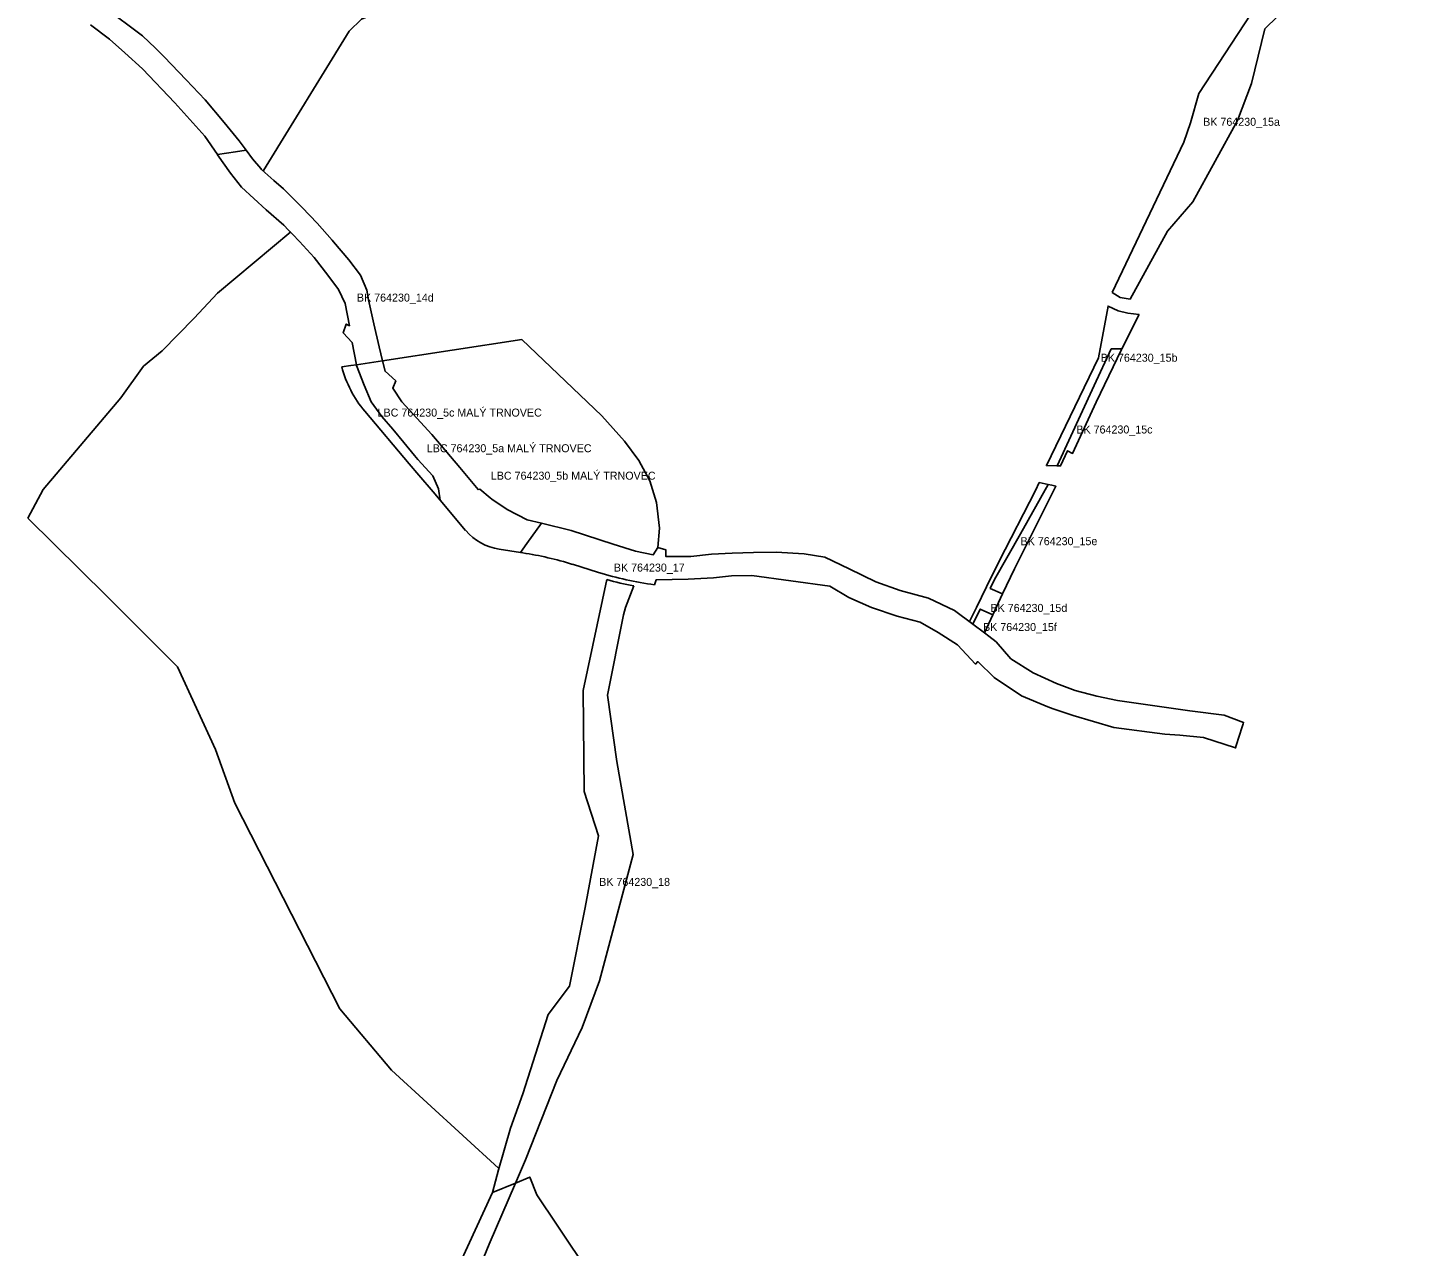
# Model space of a CAD drawing. Extents: x -521616 to -516782, y -1190061 to -1184927.
# Drawn here: x -518534 to -517316, y -1188489 to -1187423 of the extents above; entities that cross this region are included whole.
import ezdxf

# ---------------------------------------------------------------- set-up
doc = ezdxf.new("R2010")
doc.units = 0
for name, color, linetype in [('i_prvek_l_n', 7, 'Continuous'), ('i_prvek_l_s', 7, 'Continuous'), ('LBC_n', 7, 'Continuous'), ('LBC_s', 7, 'Continuous'), ('LBK_n', 7, 'Continuous'), ('LBK_s', 7, 'Continuous')]:
    doc.layers.add(name, color=color, linetype=linetype)

msp = doc.modelspace()

# ---------------------------------------------------------------- linework, layer by layer
at = {"layer": 'i_prvek_l_n'}
for points in [[(-518327.8, -1187548.3), (-518252.9, -1187426.5), (-518242, -1187415.8), (-518235, -1187412.9), (-518191.3, -1187412)], [(-518533.9, -1187852.4), (-518520.4, -1187827.3), (-518452.6, -1187747.2), (-518432.7, -1187719.6), (-518416.4, -1187706.2), (-518388.3, -1187677.4), (-518367.9, -1187655.6), (-518304, -1187602)]]:
    msp.add_lwpolyline(points, dxfattribs=at)
at = {"layer": 'i_prvek_l_s'}
msp.add_lwpolyline([(-518122.2, -1188421.1), (-518215.8, -1188335.4), (-518261.1, -1188281.7), (-518352.9, -1188101.7), (-518369.9, -1188054.9), (-518403.1, -1187982.6), (-518465.1, -1187920.5), (-518533.9, -1187852.4)], dxfattribs=at)
at = {"layer": 'LBC_n'}
for points in [[(-518223.7, -1187714.7), (-518102, -1187696.1), (-518031.8, -1187762.8), (-518012.2, -1187785.1), (-517999.6, -1187802), (-517989.8, -1187819.8), (-517984, -1187838.7), (-517981.5, -1187861.2), (-517982.9, -1187878.1), (-517987, -1187884.5), (-518002.4, -1187881.3), (-518021.9, -1187875.1), (-518058.6, -1187863.4), (-518084.7, -1187856.9), (-518097.1, -1187853.8), (-518114.6, -1187845), (-518128.2, -1187835.9), (-518129.6, -1187834.7), (-518138.5, -1187827.1), (-518140.1, -1187827.4), (-518156.2, -1187808.2), (-518180.6, -1187779.3), (-518206.7, -1187750.6), (-518214.8, -1187738.7), (-518212.1, -1187732.3), (-518221.4, -1187724)], [(-518107.5, -1188434.2), (-518094.9, -1188429), (-518088.8, -1188444.4), (-518071, -1188471), (-517982, -1188604), (-517899.2, -1188742.7), (-518042.7, -1188683.1), (-518186.2, -1188623.6), (-518130.3, -1188487.5)]]:
    msp.add_lwpolyline(points, close=True, dxfattribs=at)
msp.add_lwpolyline([(-518259.3, -1187720.1), (-518251.5, -1187718.9), (-518246.6, -1187718.2), (-518246.4, -1187718.8), (-518239.9, -1187736), (-518233.5, -1187750.6), (-518224.4, -1187763.4), (-518214.8, -1187774.7), (-518205.2, -1187786.3), (-518195.8, -1187797.6), (-518192.9, -1187801.1), (-518179.6, -1187815.4), (-518174.7, -1187826.8), (-518173.4, -1187836.7), (-518179.5, -1187829.5), (-518191.9, -1187814.8), (-518200.3, -1187804.9), (-518239.2, -1187758.9)], dxfattribs=at)
msp.add_arc((-518164.4, -1187695.6), 98, 194.4563, 220.234, dxfattribs=at)
at = {"layer": 'LBC_s'}
for points in [[(-518179.6, -1187815.4), (-518192.9, -1187801.1), (-518195.8, -1187797.6), (-518205.2, -1187786.3), (-518214.8, -1187774.7), (-518224.4, -1187763.4), (-518233.5, -1187750.6), (-518239.9, -1187736), (-518246.4, -1187718.8), (-518246.6, -1187718.2), (-518223.7, -1187714.7), (-518221.4, -1187724), (-518212.1, -1187732.3), (-518214.8, -1187738.7), (-518206.7, -1187750.6), (-518180.6, -1187779.3), (-518156.2, -1187808.2), (-518140.1, -1187827.4), (-518138.5, -1187827.1), (-518129.6, -1187834.7), (-518128.2, -1187835.9), (-518114.6, -1187845), (-518097.1, -1187853.8), (-518084.7, -1187856.9), (-518097.4, -1187874.7)], [(-518151, -1187863.2), (-518173.4, -1187836.7), (-518174.7, -1187826.8), (-518179.6, -1187815.4)], [(-518097.4, -1187874.7), (-518102.9, -1187882.5), (-518121.6, -1187879.6)], [(-518178.1, -1188552.2), (-518127.5, -1188442.4), (-518107.5, -1188434.2), (-518130.3, -1188487.5), (-518186.2, -1188623.6)]]:
    msp.add_lwpolyline(points, dxfattribs=at)
msp.add_arc((-518114.3, -1187832.2), 48, 220.2323, 261.2546, dxfattribs=at)
at = {"layer": 'LBK_n'}
for points in [[(-518352.3, -1187532), (-518343, -1187530.5), (-518337.4, -1187538), (-518330.2, -1187546.5), (-518329.5, -1187547.4), (-518326.5, -1187550.1), (-518318.7, -1187557.1), (-518310.4, -1187564.3), (-518294.1, -1187580.8), (-518281, -1187594.4), (-518267.8, -1187609.4), (-518266.5, -1187610.8), (-518253.1, -1187626.6), (-518243.1, -1187639.9), (-518237.5, -1187652.9), (-518235.9, -1187661.6), (-518231.2, -1187682.4), (-518226.7, -1187702.5), (-518223.7, -1187714.7), (-518246.6, -1187718.2), (-518250.4, -1187698.8), (-518258, -1187690.3), (-518255.4, -1187682.6), (-518252.6, -1187684.1), (-518256.3, -1187664.8), (-518262.3, -1187652.3), (-518271.6, -1187639.8), (-518283.6, -1187624.5), (-518296.4, -1187610.4), (-518302.4, -1187604), (-518304.1, -1187602.2), (-518305.9, -1187600.4), (-518310, -1187596), (-518325.6, -1187582.7), (-518336.4, -1187572.9), (-518347, -1187562.8), (-518356.8, -1187550.6), (-518367.9, -1187534.7), (-518368.1, -1187534.4)], [(-517684.5, -1187890.1), (-517652.7, -1187828.4), (-517649.4, -1187821.4), (-517641.6, -1187823), (-517665.7, -1187866.1), (-517688.4, -1187906.2), (-517692.2, -1187914), (-517681.4, -1187918.8), (-517689.8, -1187936.9), (-517701, -1187932), (-517707.4, -1187945.2), (-517710.4, -1187943), (-517704.3, -1187930.6), (-517695.5, -1187912.6)]]:
    msp.add_lwpolyline(points, close=True, dxfattribs=at)
for points in [[(-517586.4, -1187704.3), (-517601.2, -1187736.4), (-517633.7, -1187806.7), (-517643.1, -1187806.5), (-517597.6, -1187712.2), (-517589.2, -1187666.9), (-517580.3, -1187671.2), (-517572, -1187673.1)], [(-517562, -1187674.2), (-517577.2, -1187704.4), (-517586.4, -1187704.3)], [(-517572, -1187673.1), (-517562, -1187674.2)]]:
    msp.add_lwpolyline(points, dxfattribs=at)
at = {"layer": 'LBK_s'}
for points in [[(-517585.7, -1187655.1), (-517522.9, -1187523.6), (-517517, -1187506.5), (-517509.9, -1187480.8), (-517441.7, -1187376.6), (-517361.8, -1187252.7), (-517351.7, -1187237.2), (-517316.2, -1187258.5), (-517347.4, -1187309.2), (-517384.1, -1187358), (-517452.1, -1187424.5), (-517463.8, -1187472.2), (-517476, -1187504.6), (-517514.9, -1187575.8), (-517537.2, -1187601.4), (-517569.9, -1187660.8), (-517578.6, -1187659.3), (-517585.7, -1187655.1)], [(-517681.4, -1187918.8), (-517692.2, -1187914), (-517688.4, -1187906.2), (-517665.7, -1187866.1), (-517641.6, -1187823), (-517638.3, -1187823.7), (-517634.7, -1187824.6), (-517671.1, -1187896.8)], [(-517701, -1187932), (-517689.8, -1187936.9), (-517697.3, -1187952.8), (-517707.4, -1187945.2)]]:
    msp.add_lwpolyline(points, close=True, dxfattribs=at)
for points in [[(-518467.3, -1187405.3), (-518433.5, -1187430.6), (-518422.4, -1187441.4), (-518414.7, -1187448.9), (-518395.5, -1187469), (-518378.8, -1187486.6), (-518362.1, -1187506.3), (-518349.2, -1187522.3), (-518343, -1187530.5)], [(-518368.1, -1187534.4), (-518379.1, -1187518.4), (-518405.4, -1187489.2), (-518433.6, -1187459.4), (-518449.2, -1187445.4), (-518462.6, -1187433.3), (-518479, -1187420.8)], [(-518343, -1187530.5), (-518352.3, -1187532), (-518368.1, -1187534.4)], [(-517577.2, -1187704.4), (-517577.5, -1187704.9), (-517599.5, -1187750.9), (-517620.2, -1187795.8), (-517624.5, -1187793.5), (-517630.7, -1187806.8), (-517633.7, -1187806.7), (-517601.2, -1187736.4), (-517586.4, -1187704.3)], [(-517586.4, -1187704.3), (-517577.2, -1187704.4)], [(-518102.9, -1187882.5), (-518097.4, -1187874.7), (-518084.7, -1187856.9), (-518058.6, -1187863.4), (-518021.9, -1187875.1), (-518002.4, -1187881.3), (-517987, -1187884.5), (-517982.9, -1187878.1), (-517976, -1187880.1), (-517976, -1187885.9), (-517954.2, -1187886.1), (-517936, -1187884), (-517917.8, -1187883), (-517899.4, -1187882.5), (-517879.5, -1187882.2), (-517855, -1187883.6), (-517836.9, -1187886.7), (-517815.6, -1187896.7), (-517792.3, -1187908.1), (-517771, -1187915.8), (-517746.3, -1187922.6), (-517723.6, -1187933.3), (-517707.4, -1187945.2), (-517697.3, -1187952.8), (-517693.5, -1187955.7), (-517687.1, -1187960.6), (-517674.1, -1187975.4), (-517654.8, -1187987.8), (-517634.3, -1187997.2), (-517617.9, -1188003.2), (-517599, -1188008.1), (-517580.9, -1188012), (-517542, -1188017.5), (-517517.6, -1188020.9), (-517487.7, -1188024.8), (-517470.7, -1188031.1), (-517471.1, -1188032.5), (-517471.9, -1188034.9), (-517477, -1188051.4), (-517477.6, -1188053.5), (-517477.6, -1188053.5), (-517505.7, -1188044.4), (-517526.3, -1188042.2), (-517539.4, -1188041.4), (-517584.1, -1188035.7), (-517619.8, -1188025.2), (-517637.1, -1188019.4), (-517641.7, -1188017.5), (-517664.8, -1188007.8), (-517688.9, -1187991.9), (-517703.1, -1187977.9), (-517705, -1187980.2), (-517720.9, -1187963.2), (-517737.8, -1187952.4), (-517753.4, -1187943.6), (-517773.5, -1187938.1), (-517796, -1187930.5), (-517815.8, -1187921.9), (-517832.6, -1187912), (-517900.7, -1187902.6), (-517918.4, -1187902.9), (-517934.3, -1187904.6), (-517956.5, -1187905.8), (-517984.5, -1187906.5), (-517985.9, -1187910.7)], [(-518101.1, -1187882.8), (-518102.9, -1187882.5)], [(-518034.7, -1187899.9), (-518057.5, -1187892.8)], [(-518004, -1187911.7), (-518011.1, -1187930.6), (-518012.9, -1187936.9), (-518026.9, -1188007.2), (-518018.9, -1188065.3), (-518004.4, -1188146.7), (-518034, -1188257.2), (-518049.1, -1188298), (-518071.3, -1188344.3), (-518098.8, -1188413.7), (-518107.5, -1188434.2), (-518127.5, -1188442.4), (-518122.4, -1188422.6), (-518111.9, -1188386), (-518101, -1188356.2), (-518078.7, -1188286.6), (-518060.2, -1188261.9), (-518046.6, -1188193), (-518034.8, -1188130.3), (-518047.3, -1188091.6), (-518048.2, -1188003.1), (-518027.6, -1187906.2)]]:
    msp.add_lwpolyline(points, dxfattribs=at)
for centre, radius, start, end in [((-518147, -1188181.3), 302, 72.7538, 81.2533), ((-517946.4, -1187615.3), 298, 252.7538, 262.3877), ((-517946.4, -1187615.3), 302, 254.3944, 258.9931)]:
    msp.add_arc(centre, radius, start, end, dxfattribs=at)

# ---------------------------------------------------------------- texts
at = {"layer": 'LBC_n'}
for s, p in [('LBC 764230_5c MALÝ TRNOVEC', (-518228, -1187763.6)), ('LBC 764230_5b MALÝ TRNOVEC', (-518129, -1187818.8))]:
    msp.add_text(s, height=7, dxfattribs=at).set_placement(p)
at = {"layer": 'LBC_s'}
msp.add_text('LBC 764230_5a MALÝ TRNOVEC', height=7, dxfattribs=at).set_placement((-518185, -1187794.8))
at = {"layer": 'LBK_n'}
for s, p in [('BK 764230_14d', (-518246.1, -1187663)), ('BK 764230_15b', (-517595.6, -1187715.6)), ('BK 764230_15d', (-517692, -1187934.5))]:
    msp.add_text(s, height=7, dxfattribs=at).set_placement(p)
at = {"layer": 'LBK_s'}
for s, p in [('BK 764230_15a', (-517506, -1187509.2)), ('BK 764230_15c', (-517616.9, -1187778.4)), ('BK 764230_15e', (-517665.7, -1187876.1)), ('BK 764230_17', (-518021.4, -1187899.2)), ('BK 764230_15f', (-517698.5, -1187951.2)), ('BK 764230_18', (-518034.2, -1188174.2))]:
    msp.add_text(s, height=7, dxfattribs=at).set_placement(p)

doc.saveas('drawing.dxf')
